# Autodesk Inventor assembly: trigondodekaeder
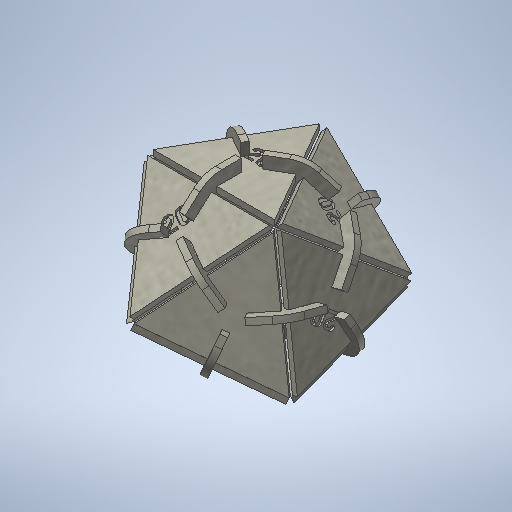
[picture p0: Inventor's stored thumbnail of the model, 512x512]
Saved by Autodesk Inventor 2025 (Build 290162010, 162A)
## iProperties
Created: 2025-02
Part Number: trigondodekaeder
Material: Generisch
Document SubType Name: Assembly
Designer: BennF
Author: BennF
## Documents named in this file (4)
- C:\Users\BennF\OneDrive - Technische Universität Ilmenau\FabAcademy\week03\trigondodekaeder.iam
- C:\Users\BennF\OneDrive - Technische Universität Ilmenau\FabAcademy\week03\triangular_tile.ipt
- C:\Users\BennF\OneDrive - Technische Universität Ilmenau\FabAcademy\week03\conector_138.ipt
- C:\Users\BennF\OneDrive - Technische Universität Ilmenau\FabAcademy\week03\conector_75.ipt
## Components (25 placed, 3 different names)
1. triangular_tile:1 — Mate:1, Mate:2, Mate:3, Mate:27, Mate:70, Mate:71, Mate:72
2. triangular_tile:2
3. triangular_tile:3
4. triangular_tile:4
5. triangular_tile:5
6. triangular_tile:6 — Mate:76, Mate:77, Mate:78, Mate:91, Mate:92, Mate:93
7. triangular_tile:7 — Mate:79, Mate:80, Mate:81, Mate:94, Mate:95, Mate:96
8. triangular_tile:8 — Mate:82, Mate:83, Mate:84, Mate:97, Mate:98, Mate:99
9. triangular_tile:9 — Mate:85, Mate:86, Mate:87, Mate:100, Mate:101, Mate:102
10. triangular_tile:10 — Mate:88, Mate:89, Mate:90, Mate:103, Mate:104, Mate:105
11. conector_138:1 — Mate:1, Mate:2, Mate:3, Mate:4, Mate:5, Mate:6
12. conector_138:2 — Mate:7, Mate:8, Mate:9, Mate:10, Mate:11, Mate:12
13. conector_138:3 — Mate:13, Mate:14, Mate:15, Mate:16, Mate:17, Mate:18
14. conector_138:4 — Mate:19, Mate:20, Mate:21, Mate:22, Mate:23, Mate:24
15. conector_138:5 — Mate:25, Mate:26, Mate:27
16. conector_138:6 — Mate:91, Mate:92, Mate:93
17. conector_138:7 — Mate:94, Mate:95, Mate:96
18. conector_138:8 — Mate:97, Mate:98, Mate:99
19. conector_138:9 — Mate:100, Mate:101, Mate:102
20. conector_138:10 — Mate:103, Mate:104, Mate:105
21. conector_75:1 — Mate:61, Mate:62, Mate:63, Mate:85, Mate:86, Mate:87
22. conector_75:2 — Mate:64, Mate:65, Mate:66, Mate:82, Mate:83, Mate:84
23. conector_75:3 — Mate:67, Mate:68, Mate:69, Mate:79, Mate:80, Mate:81
24. conector_75:4 — Mate:70, Mate:71, Mate:72, Mate:76, Mate:77, Mate:78
25. conector_75:5 — Mate:73, Mate:74, Mate:75, Mate:88, Mate:89, Mate:90
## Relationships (72: Mate 72)
- Mate:1: triangular_tile:1 ↔ conector_138:1
- Mate:2: triangular_tile:1 ↔ conector_138:1
- Mate:3: triangular_tile:1 ↔ conector_138:1
- Mate:4: conector_138:1
- Mate:5: conector_138:1
- Mate:6: conector_138:1
- Mate:7: conector_138:2
- Mate:8: conector_138:2
- Mate:9: conector_138:2
- Mate:10: conector_138:2
- Mate:11: conector_138:2
- Mate:12: conector_138:2
- Mate:13: conector_138:3
- Mate:14: conector_138:3
- Mate:15: conector_138:3
- Mate:16: conector_138:3
- Mate:17: conector_138:3
- Mate:18: conector_138:3
- Mate:19: conector_138:4
- Mate:20: conector_138:4
- Mate:21: conector_138:4
- Mate:22: conector_138:4
- Mate:23: conector_138:4
- Mate:24: conector_138:4
- Mate:25: conector_138:5
- Mate:26: conector_138:5
- Mate:27: triangular_tile:1 ↔ conector_138:5
- Mate:61: conector_75:1
- Mate:62: conector_75:1
- Mate:63: conector_75:1
- Mate:64: conector_75:2
- Mate:65: conector_75:2
- Mate:66: conector_75:2
- Mate:67: conector_75:3
- Mate:68: conector_75:3
- Mate:69: conector_75:3
- Mate:70: triangular_tile:1 ↔ conector_75:4
- Mate:71: triangular_tile:1 ↔ conector_75:4
- Mate:72: triangular_tile:1 ↔ conector_75:4
- Mate:73: conector_75:5
- Mate:74: conector_75:5
- Mate:75: conector_75:5
- Mate:76: triangular_tile:6 ↔ conector_75:4
- Mate:77: triangular_tile:6 ↔ conector_75:4
- Mate:78: triangular_tile:6 ↔ conector_75:4
- Mate:79: triangular_tile:7 ↔ conector_75:3
- Mate:80: triangular_tile:7 ↔ conector_75:3
- Mate:81: triangular_tile:7 ↔ conector_75:3
- Mate:82: triangular_tile:8 ↔ conector_75:2
- Mate:83: triangular_tile:8 ↔ conector_75:2
- Mate:84: triangular_tile:8 ↔ conector_75:2
- Mate:85: triangular_tile:9 ↔ conector_75:1
- Mate:86: triangular_tile:9 ↔ conector_75:1
- Mate:87: triangular_tile:9 ↔ conector_75:1
- Mate:88: triangular_tile:10 ↔ conector_75:5
- Mate:89: triangular_tile:10 ↔ conector_75:5
- Mate:90: triangular_tile:10 ↔ conector_75:5
- Mate:91: triangular_tile:6 ↔ conector_138:6
- Mate:92: triangular_tile:6 ↔ conector_138:6
- Mate:93: triangular_tile:6 ↔ conector_138:6
- Mate:94: triangular_tile:7 ↔ conector_138:7
- Mate:95: triangular_tile:7 ↔ conector_138:7
- Mate:96: triangular_tile:7 ↔ conector_138:7
- Mate:97: triangular_tile:8 ↔ conector_138:8
- Mate:98: triangular_tile:8 ↔ conector_138:8
- Mate:99: triangular_tile:8 ↔ conector_138:8
- Mate:100: triangular_tile:9 ↔ conector_138:9
- Mate:101: triangular_tile:9 ↔ conector_138:9
- Mate:102: triangular_tile:9 ↔ conector_138:9
- Mate:103: triangular_tile:10 ↔ conector_138:10
- Mate:104: triangular_tile:10 ↔ conector_138:10
- Mate:105: triangular_tile:10 ↔ conector_138:10
